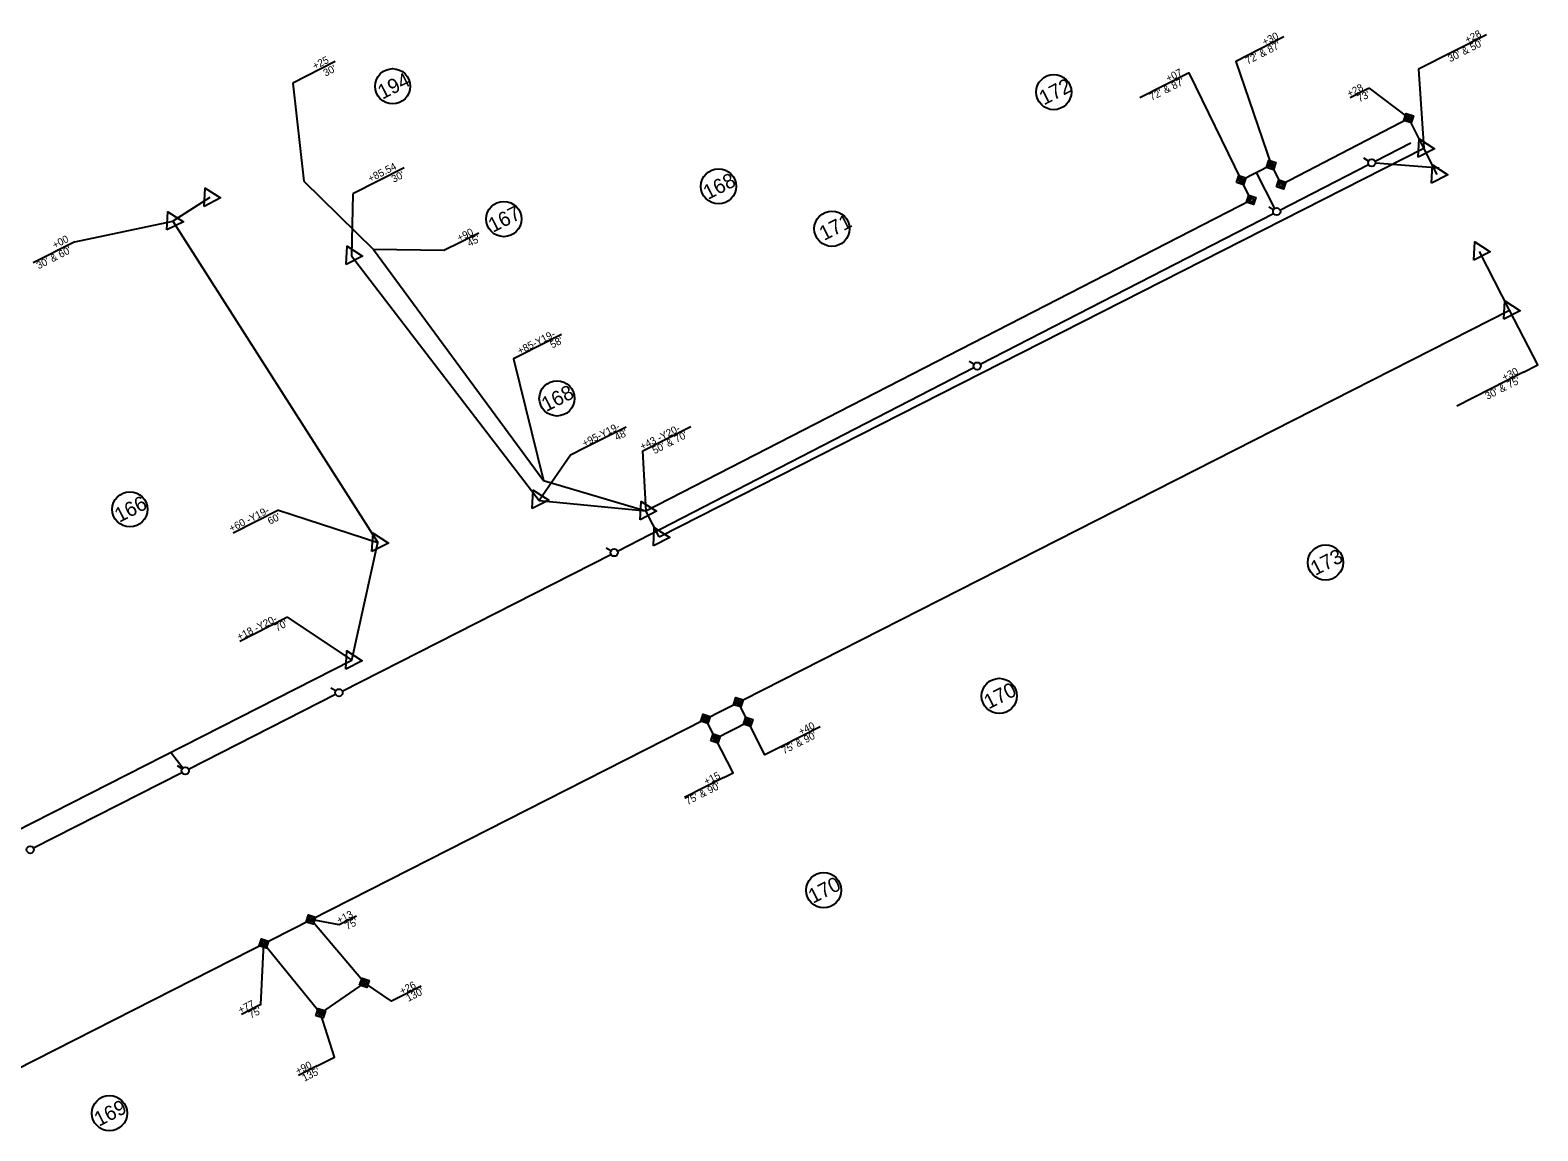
# Model space of a CAD drawing. Extents: x 2320946 to 2332748, y 597838 to 612698.
# Drawn here: x 2331720 to 2332748, y 611947 to 612698 of the extents above; entities that cross this region are included whole.
import ezdxf

# ---------------------------------------------------------------- set-up
doc = ezdxf.new("R2010")
doc.units = 0
for name, color, linetype in [('Prop Easement Construction', 7, 'Continuous'), ('Prop Easement Construction Station Offsets', 7, 'Continuous'), ('Prop Easement Permanent Drainage Utility', 7, 'Continuous'), ('Prop Easement Permanent Drainage Utility Station Offsets', 7, 'Continuous'), ('Prop Easement Permanent Utility', 7, 'Continuous'), ('Prop Easement Permanent Utility Station Offsets', 7, 'Continuous'), ('Prop Parcel Number CELL', 7, 'Continuous'), ('Prop ROW Marker CELL', 7, 'Continuous'), ('Prop ROW Permanent Easement CELL', 7, 'Continuous'), ('Prop ROW RW Lines', 7, 'Continuous'), ('Prop ROW Station Offsets', 7, 'Continuous'), ('Scratch_Level_1', 7, 'Continuous')]:
    doc.layers.add(name, color=color, linetype=linetype)

msp = doc.modelspace()

# ---------------------------------------------------------------- linework, layer by layer
at = {"layer": 'Prop Easement Construction'}
for p, q in [((2331906.8, 612594.7), (2331954.4, 612548)), ((2331954.4, 612548), (2332070.2, 612390.6)), ((2332070.2, 612390.6), (2332140, 612369.9))]:
    msp.add_line(p, q, dxfattribs=at)
at = {"layer": 'Prop Easement Construction Station Offsets'}
for p, q in [((2331928.3, 612676.3), (2331899.3, 612661.5)), ((2332026.1, 612559.3), (2332013.5, 612552.9)), ((2332082.5, 612490), (2332054.4, 612475.7))]:
    msp.add_line(p, q, dxfattribs=at)
for points in [[(2331899.3, 612661.5), (2331906.8, 612594.7), (2331907, 612594.4)], [(2332013.5, 612552.9), (2332002.4, 612547.3), (2331954.4, 612548)], [(2332054.4, 612475.7), (2332049.8, 612473.4), (2332070.2, 612390.6)]]:
    msp.add_lwpolyline(points, dxfattribs=at)
at = {"layer": 'Prop Easement Permanent Drainage Utility'}
for p, q in [((2331948.1, 612047.9), (2331911.6, 612091.1)), ((2331879.5, 612074.8), (2331918.3, 612027.2)), ((2331948.1, 612047.9), (2331918.3, 612027.2))]:
    msp.add_line(p, q, dxfattribs=at)
at = {"layer": 'Prop Easement Permanent Drainage Utility Station Offsets'}
for p, q in [((2331942.7, 612093.4), (2331931.3, 612087.6)), ((2331986.8, 612045.7), (2331974.3, 612039.3)), ((2331877, 612032.9), (2331864.3, 612026.4)), ((2331915.9, 611991.2), (2331903.3, 611984.8))]:
    msp.add_line(p, q, dxfattribs=at)
for points in [[(2331931.3, 612087.6), (2331931, 612087.4), (2331911.6, 612091.1)], [(2331877, 612032.9), (2331877.4, 612033.1), (2331879.5, 612074.8)], [(2331974.3, 612039.3), (2331966.7, 612035.4), (2331948.1, 612047.9)], [(2331915.9, 611991.2), (2331927.8, 611997.2), (2331918.3, 612027.2)]]:
    msp.add_lwpolyline(points, dxfattribs=at)
at = {"layer": 'Prop Easement Permanent Utility'}
for p, q in [((2332573.3, 612592.4), (2332660.2, 612637.7)), ((2332670.6, 612617.2), (2332660.2, 612637.7)), ((2332546, 612595.3), (2332566.5, 612605.7)), ((2332566.5, 612605.7), (2332573.3, 612592.4)), ((2332552.8, 612581.9), (2332546, 612595.3)), ((2332140, 612369.9), (2332552.8, 612581.9)), ((2332209.9, 612225.9), (2332203.1, 612239.3)), ((2332187.6, 612214.6), (2332180.8, 612227.9)), ((2332187.6, 612214.6), (2332209.9, 612225.9))]:
    msp.add_line(p, q, dxfattribs=at)
at = {"layer": 'Prop Easement Permanent Utility Station Offsets'}
for p, q in [((2332575.1, 612693), (2332542.4, 612676.3)), ((2332509.6, 612668.2), (2332476.8, 612651.6)), ((2332632.9, 612657.8), (2332620.3, 612651.4)), ((2332258.8, 612222.5), (2332232, 612208.9)), ((2332193.2, 612188), (2332166.3, 612174.3))]:
    msp.add_line(p, q, dxfattribs=at)
for points in [[(2332542.4, 612676.3), (2332542.3, 612676.3), (2332566.5, 612605.7)], [(2332509.6, 612668.2), (2332510.2, 612668.5), (2332546, 612595.3)], [(2332632.9, 612657.8), (2332633.3, 612658), (2332660.2, 612637.7)], [(2332232, 612208.9), (2332221.1, 612203.4), (2332209.9, 612225.9)], [(2332193.2, 612188), (2332199.5, 612191.2), (2332187.6, 612214.6)]]:
    msp.add_lwpolyline(points, dxfattribs=at)
at = {"layer": 'Prop Parcel Number CELL'}
for p, q in [((2331967.4, 612659.4), (2331967.4, 612659.4)), ((2332418.2, 612655.4), (2332418.2, 612655.4)), ((2332189.6, 612591.1), (2332189.6, 612591.1)), ((2332043.2, 612568.8), (2332043.2, 612568.8)), ((2332266.9, 612562.2), (2332266.9, 612562.2)), ((2332079.4, 612446.5), (2332079.4, 612446.5)), ((2331788.2, 612370.9), (2331788.2, 612370.9)), ((2332603.5, 612334.6), (2332603.5, 612334.6)), ((2332381, 612243.6), (2332381, 612243.6)), ((2332261.3, 612111.1), (2332261.3, 612111.1)), ((2331774.3, 611959), (2331774.3, 611959))]:
    msp.add_line(p, q, dxfattribs=at)
for centre in [(2331967.4, 612659.4), (2332418.2, 612655.4), (2332189.6, 612591.1), (2332043.2, 612568.8), (2332266.9, 612562.2), (2332079.4, 612446.5), (2331788.2, 612370.9), (2332603.5, 612334.6), (2332381, 612243.6), (2332261.3, 612111.1), (2331774.3, 611959)]:
    msp.add_circle(centre, 12, dxfattribs=at)
at = {"layer": 'Prop ROW Marker CELL'}
for p, q in [((2332660.2, 612637.7), (2332660.2, 612637.7)), ((2332670.6, 612617.2), (2332670.6, 612617.2)), ((2332566.5, 612605.7), (2332566.5, 612605.7)), ((2332546, 612595.3), (2332546, 612595.3)), ((2332573.3, 612592.4), (2332573.3, 612592.4)), ((2332679.7, 612599.3), (2332679.7, 612599.3)), ((2331842.8, 612583.5), (2331842.8, 612583.5)), ((2332552.8, 612581.9), (2332552.8, 612581.9)), ((2331817.5, 612567.4), (2331817.5, 612567.4)), ((2331939.6, 612543.8), (2331939.6, 612543.8)), ((2332708.6, 612546.7), (2332708.6, 612546.7)), ((2332729, 612506.6), (2332729, 612506.6)), ((2332066.6, 612377.6), (2332066.6, 612377.6)), ((2332140, 612369.9), (2332140, 612369.9)), ((2331957.3, 612348.2), (2331957.3, 612348.2)), ((2332149.1, 612352.1), (2332149.1, 612352.1)), ((2331939.5, 612267.9), (2331939.5, 612267.9)), ((2332203.1, 612239.3), (2332203.1, 612239.3)), ((2332180.8, 612227.9), (2332180.8, 612227.9)), ((2332209.9, 612225.9), (2332209.9, 612225.9)), ((2332187.6, 612214.6), (2332187.6, 612214.6)), ((2331911.6, 612091.1), (2331911.6, 612091.1)), ((2331879.5, 612074.8), (2331879.5, 612074.8)), ((2331948.1, 612047.9), (2331948.1, 612047.9)), ((2331918.3, 612027.2), (2331918.3, 612027.2))]:
    msp.add_line(p, q, dxfattribs=at)
for points in [[(2332666.7, 612611.1), (2332667.3, 612623.6), (2332677.8, 612616.8)], [(2332675.7, 612593.3), (2332676.4, 612605.7), (2332686.9, 612598.9)], [(2331838.8, 612577.5), (2331839.5, 612590), (2331850, 612583.2)], [(2331813.5, 612561.4), (2331814.2, 612573.8), (2331824.7, 612567)], [(2332704.7, 612540.7), (2332705.4, 612553.2), (2332715.8, 612546.4)], [(2331935.7, 612537.8), (2331936.4, 612550.3), (2331946.8, 612543.5)], [(2332725.1, 612500.6), (2332725.8, 612513), (2332736.2, 612506.3)], [(2332062.6, 612371.5), (2332063.3, 612384), (2332073.8, 612377.2)], [(2332136.1, 612363.8), (2332136.8, 612376.3), (2332147.2, 612369.5)], [(2332145.2, 612346), (2332145.8, 612358.5), (2332156.3, 612351.7)], [(2331953.3, 612342.2), (2331954, 612354.6), (2331964.5, 612347.8)], [(2331935.5, 612261.9), (2331936.2, 612274.3), (2331946.7, 612267.5)]]:
    msp.add_lwpolyline(points, close=True, dxfattribs=at)
at = {"layer": 'Prop ROW Permanent Easement CELL'}
for points in [[(2332657, 612636), (2332658.5, 612640.9), (2332663.4, 612639.3), (2332661.8, 612634.4)], [(2332658.6, 612636.8), (2332659.4, 612639.3), (2332661.8, 612638.5), (2332661, 612636)], [(2332563.3, 612604.1), (2332564.8, 612608.9), (2332569.7, 612607.4), (2332568.1, 612602.5)], [(2332564.9, 612604.9), (2332565.7, 612607.3), (2332568.1, 612606.5), (2332567.3, 612604.1)], [(2332542.8, 612593.7), (2332544.3, 612598.5), (2332549.2, 612596.9), (2332547.6, 612592.1)], [(2332544.4, 612594.5), (2332545.1, 612596.9), (2332547.6, 612596.1), (2332546.8, 612593.7)], [(2332570.1, 612590.7), (2332571.6, 612595.6), (2332576.5, 612594), (2332574.9, 612589.1)], [(2332571.7, 612591.5), (2332572.4, 612594), (2332574.9, 612593.2), (2332574.1, 612590.7)], [(2332549.6, 612580.3), (2332551.1, 612585.1), (2332556, 612583.6), (2332554.4, 612578.7)], [(2332551.2, 612581.1), (2332551.9, 612583.5), (2332554.4, 612582.7), (2332553.6, 612580.3)], [(2332199.9, 612237.6), (2332201.4, 612242.5), (2332206.3, 612240.9), (2332204.7, 612236.1)], [(2332201.5, 612238.4), (2332202.3, 612240.9), (2332204.7, 612240.1), (2332203.9, 612237.7)], [(2332177.6, 612226.3), (2332179.2, 612231.1), (2332184, 612229.6), (2332182.4, 612224.7)], [(2332179.2, 612227.1), (2332180, 612229.5), (2332182.4, 612228.8), (2332181.6, 612226.3)], [(2332206.7, 612224.3), (2332208.2, 612229.1), (2332213.1, 612227.5), (2332211.5, 612222.7)], [(2332208.3, 612225.1), (2332209.1, 612227.5), (2332211.5, 612226.7), (2332210.7, 612224.3)], [(2332184.4, 612212.9), (2332186, 612217.8), (2332190.8, 612216.2), (2332189.2, 612211.4)], [(2332186, 612213.7), (2332186.8, 612216.2), (2332189.2, 612215.4), (2332188.4, 612213)], [(2331908.4, 612089.4), (2331909.9, 612094.3), (2331914.8, 612092.7), (2331913.2, 612087.9)], [(2331910, 612090.3), (2331910.8, 612092.7), (2331913.2, 612091.9), (2331912.4, 612089.5)], [(2331876.3, 612073.1), (2331877.9, 612078), (2331882.7, 612076.4), (2331881.1, 612071.6)], [(2331877.9, 612074), (2331878.7, 612076.4), (2331881.1, 612075.6), (2331880.3, 612073.2)], [(2331944.9, 612046.3), (2331946.5, 612051.2), (2331951.3, 612049.6), (2331949.7, 612044.7)], [(2331946.5, 612047.1), (2331947.3, 612049.5), (2331949.7, 612048.8), (2331948.9, 612046.3)], [(2331915.1, 612025.5), (2331916.6, 612030.4), (2331921.5, 612028.8), (2331919.9, 612024)], [(2331916.7, 612026.4), (2331917.5, 612028.8), (2331919.9, 612028), (2331919.1, 612025.6)]]:
    msp.add_lwpolyline(points, close=True, dxfattribs=at)
at = {"layer": 'Prop ROW RW Lines'}
for p, q in [((2332149.1, 612352.1), (2332670.6, 612617.2)), ((2332679.7, 612599.3), (2332670.6, 612617.2)), ((2331842.8, 612583.5), (2331817.5, 612567.4)), ((2331817.5, 612567.4), (2331957.3, 612348.2)), ((2331939.3, 612543.7), (2332067.2, 612376.8)), ((2332729, 612506.6), (2332708.6, 612546.7)), ((2331686.8, 611976.8), (2332729, 612506.6)), ((2332067.2, 612376.8), (2332140, 612369.9)), ((2332149.1, 612352.1), (2332140, 612369.9)), ((2331939.5, 612267.9), (2331957.3, 612348.2)), ((2331621.1, 612106.1), (2331939.5, 612267.9))]:
    msp.add_line(p, q, dxfattribs=at)
at = {"layer": 'Prop ROW Station Offsets'}
for p, q in [((2332713.2, 612694.5), (2332667.3, 612671.2)), ((2331975.3, 612603.8), (2331940.3, 612586)), ((2331940.3, 612586), (2331939.3, 612543.7)), ((2331750.7, 612553.3), (2331722.3, 612538.9)), ((2332738.5, 612464.3), (2332693.1, 612441.2)), ((2332170.7, 612427.2), (2332137.9, 612410.6)), ((2332126.6, 612427), (2332098.4, 612412.7)), ((2331889.6, 612370.2), (2331858.7, 612354.5)), ((2331889.6, 612370.2), (2331957.3, 612348.2)), ((2331894.8, 612296.9), (2331863.1, 612280.8))]:
    msp.add_line(p, q, dxfattribs=at)
for points in [[(2332667.3, 612671.2), (2332666.9, 612671), (2332670.6, 612617.2)], [(2331750.7, 612553.3), (2331817.5, 612567.4)], [(2332738.5, 612464.3), (2332748.3, 612469.3), (2332729, 612506.6)], [(2332098.4, 612412.7), (2332088.7, 612407.7), (2332067.2, 612376.8)], [(2332137.9, 612410.6), (2332137.8, 612410.5), (2332140, 612369.9)], [(2331894.8, 612296.9), (2331895.4, 612297.2), (2331939.5, 612267.9)]]:
    msp.add_lwpolyline(points, dxfattribs=at)
at = {"layer": 'Scratch_Level_1'}
for p, q in [((2332637.3, 612608.3), (2332661.7, 612620.9)), ((2332632.9, 612608.4), (2332629.6, 612610.3)), ((2332681.1, 612603.6), (2332637.5, 612607)), ((2332569, 612576.1), (2332556.5, 612600.6)), ((2332368.1, 612469.8), (2332568, 612572.7)), ((2332568, 612575.1), (2332564.8, 612577)), ((2332363.7, 612469.9), (2332360.4, 612471.7)), ((2332120.6, 612342.4), (2332363.6, 612467.5)), ((2331933, 612246.9), (2332116.1, 612340.1)), ((2332116.2, 612342.5), (2332112.9, 612344.4)), ((2331928.6, 612247), (2331925.3, 612248.9)), ((2331824.4, 612194.4), (2331816.7, 612204.3)), ((2331823.9, 612193.9), (2331820.7, 612195.9))]:
    msp.add_line(p, q, dxfattribs=at)
for points in [[(2332572.4, 612575), (2332632.8, 612606.1)], [(2331828.2, 612193.6), (2331928.5, 612244.7)], [(2331722.5, 612139.9), (2331823.7, 612191.3)]]:
    msp.add_lwpolyline(points, dxfattribs=at)
for centre in [(2332635, 612607.2), (2332570.2, 612573.9), (2332365.9, 612468.6), (2332118.4, 612341.3), (2331930.8, 612245.8), (2331826, 612192.5), (2331720.3, 612138.7)]:
    msp.add_circle(centre, 2.5, dxfattribs=at)

# ---------------------------------------------------------------- texts
at = {"layer": 'Prop Easement Construction Station Offsets'}
for s, rotation, p in [('+25', 26.947, (2331914.3, 612670.6)), ("30'", 26.947, (2331921.6, 612665.9)), ('+90', 26.9454, (2332012.9, 612553.3)), ("45'", 26.9454, (2332019.8, 612549.8)), ('+85-Y19-', 26.9454, (2332054.1, 612476.3)), ("58'", 26.9454, (2332076.3, 612480.5))]:
    msp.add_text(s, height=5, rotation=rotation, dxfattribs=at).set_placement(p)
at = {"layer": 'Prop Easement Permanent Drainage Utility Station Offsets'}
for s, p in [('+13', (2331930.8, 612088)), ("75'", (2331936.4, 612083.9)), ('+26', (2331973.7, 612039.7)), ("130'", (2331978.1, 612034.9)), ('+77', (2331863.6, 612026.8)), ("75'", (2331870.7, 612023.4)), ('+90', (2331902.7, 611985.2)), ("135'", (2331907.2, 611980.4))]:
    msp.add_text(s, height=5, rotation=26.9465, dxfattribs=at).set_placement(p)
at = {"layer": 'Prop Easement Permanent Utility Station Offsets'}
for s, rotation, p in [('+30', 26.9454, (2332561.9, 612687)), ("72' & 87'", 26.9454, (2332550.4, 612674.1)), ("72' & 87'", 26.9454, (2332484.9, 612649.4)), ('+07', 26.9454, (2332496.2, 612662.1)), ('+28', 26.9454, (2332619.7, 612651.8)), ("73'", 26.9454, (2332626.6, 612648.3)), ('+40', 26.947, (2332245.7, 612216.6)), ("75' & 90'", 26.947, (2332234.2, 612203.7)), ('+15', 26.947, (2332181.2, 612182.6)), ("75' & 90'", 26.947, (2332168.5, 612169.1))]:
    msp.add_text(s, height=5, rotation=rotation, dxfattribs=at).set_placement(p)
at = {"layer": 'Prop Parcel Number CELL'}
for s, p in [('194', (2331960.4, 612650.2)), ('172', (2332411.5, 612646.3)), ('168', (2332182.4, 612581.8)), ('167', (2332035.8, 612559.4)), ('171', (2332261.5, 612553.8)), ('168', (2332072.1, 612437.2)), ('166', (2331781, 612361.6)), ('173', (2332596.5, 612325.4)), ('170', (2332373.8, 612234.3)), ('170', (2332254, 612101.8)), ('169', (2331767.1, 611949.7))]:
    msp.add_text(s, height=10, rotation=26.9454, dxfattribs=at).set_placement(p)
at = {"layer": 'Prop ROW Station Offsets'}
for s, rotation, p in [('+28 ', 26.9454, (2332700.1, 612688.5)), ("30' & 50'", 26.9454, (2332688.5, 612675.7)), ('+85.54', 26.947, (2331952.1, 612593.8)), ("30'", 26.947, (2331968.1, 612593.5)), ('+00', 26.947, (2331736.9, 612548.5)), ("30' & 60'", 26.947, (2331726, 612534.5)), ("30' & 75'", 26.9465, (2332713.9, 612445.5)), ('+30', 26.9465, (2332725.4, 612458.3)), ('+95-Y19-', 26.9454, (2332098.2, 612413.3)), ('+43 -Y20-', 26.9454, (2332137.6, 612411.1)), ("48'", 26.9454, (2332120.3, 612417.5)), ("50' & 70'", 26.9454, (2332146, 612408.4)), ('+60 -Y19-', 26.947, (2331857.4, 612355.2)), ("60'", 26.947, (2331883.7, 612360.2)), ('+18 -Y20-', 26.9454, (2331862.8, 612281.3)), ("70'", 26.9454, (2331888.5, 612287.4))]:
    msp.add_text(s, height=5, rotation=rotation, dxfattribs=at).set_placement(p)

doc.saveas('drawing.dxf')
